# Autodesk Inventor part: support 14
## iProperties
Shininess: 20.0
Angle Display Precision: 2
Document Length Units: 11269
Document Angle Units: 11279
Document Time Units: 11290
Document Mass Units: 11283
Document Length Units Precision: 3
Document Angle Units Precision: 2
Compacted: True
Created: 2002-04
Part Number: support 14
Material: Par défaut
Document SubType Name: Modélisation
Designer: thchene
Density: 0.0
Volumn: 0.0
Area: 0.0
PropertySet Name: Model Information
Control State: 0
Master: False
Checked Out: False
Author: thchene
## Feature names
1. Révolution1 [Revolution]
2. Extrusion1
3. Symétrie1 [Mirror]
4. Extrusion2
5. Extrusion3
6. Extrusion4
7. Extrusion5
8. Extrusion6
9. Extrusion7
10. Extrusion8
11. Extrusion9
12. Lissage1
